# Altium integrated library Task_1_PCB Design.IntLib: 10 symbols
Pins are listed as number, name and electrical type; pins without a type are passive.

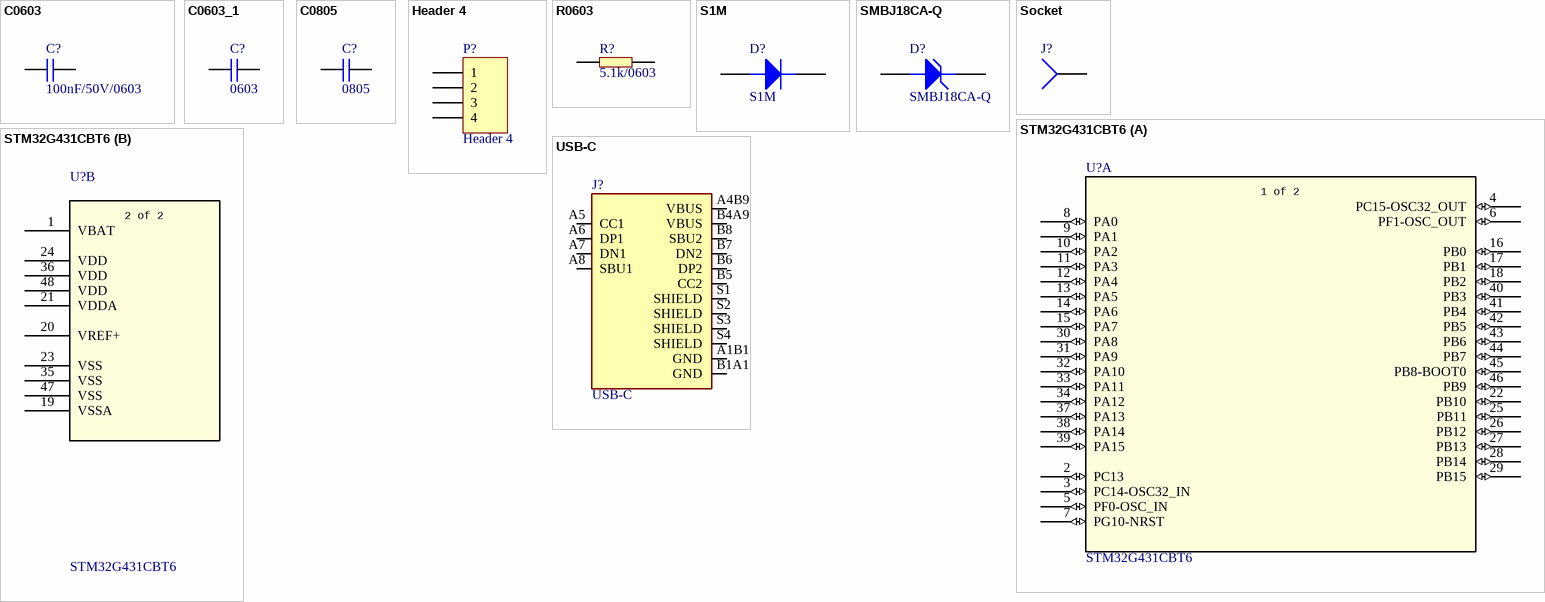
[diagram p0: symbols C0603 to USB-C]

## C0603
designator C?, comment 100nF/50V/0603
footprint C0603
pins: 1, 2

## C0603_1
designator C?, comment 0603
footprint C0603
pins: 1, 2

## C0805
designator C?, comment 0805
footprint C0805
pins: 1, 2

## Header 4
designator P?
Header, 4-Pin
footprint HDR1X4 (Connector; Header; 4 Position)
signal-integrity model Connector
pins: 1, 2, 3, 4

## R0603
designator R?, comment 5.1k/0603
footprint R0603
pins: 1, 2

## S1M
designator D?
VR=1000V IF=1A 6.6pF Trr=1.8us P=1.4W; Manufacturer: ON Semiconductor / Fairchild; Max Reverse Current: 1uA; Recovery Time: 1800ns; Forward Voltage: 1V; Forward Current: 1A; Reverse Recovery Time: 1.8us; Max Repetitive Reverse Voltage (Vrrm): 1kV; Peak Non-Repetitive Surge Current: 30A; Max Surge Current: 40A; Element Configuration: Single; Polarity: Standard; Capacitance: 12pF; Power Dissipation: 1.4W
footprint S1M
pins: A, K

## SMBJ18CA-Q
designator D?
footprint SMBJ18CA-Q
pins: A, K

## Socket
designator J?  (value not drawn)
footprint PIN1 (Connector; Socket)
signal-integrity model Connector
pins: 1

## STM32G431CBT6
designator U?
Mainstream Arm Cortex-M4 MCU 170 MHz with 128 Kbytes of Flash memory, Math Accelerator, Medium Analog level integration; Manufacturer_Name: STMicroelectronics
footprint LQFP48-7x7mm
part A pins: 2 PC13 (io), 3 PC14-OSC32_IN (io), 4 PC15-OSC32_OUT (io), 5 PF0-OSC_IN (io), 6 PF1-OSC_OUT (io), 7 PG10-NRST (io), 8 PA0 (io), 9 PA1 (io), 10 PA2 (io), 11 PA3 (io), 12 PA4 (io), 13 PA5 (io), 14 PA6 (io), 15 PA7 (io), 16 PB0 (io), 17 PB1 (io), 18 PB2 (io), 22 PB10 (io), 25 PB11 (io), 26 PB12 (io), 27 PB13 (io), 28 PB14 (io), 29 PB15 (io), 30 PA8 (io), 31 PA9 (io), 32 PA10 (io), 33 PA11 (io), 34 PA12 (io), 37 PA13 (io), 38 PA14 (io), 39 PA15 (io), 40 PB3 (io), 41 PB4 (io), 42 PB5 (io), 43 PB6 (io), 44 PB7 (io), 45 PB8-BOOT0 (io), 46 PB9 (io)
part B pins: 1 VBAT (power), 19 VSSA (power), 20 VREF+ (power), 21 VDDA (power), 23 VSS (power), 24 VDD (power), 35 VSS (power), 36 VDD (power), 47 VSS (power), 48 VDD (power)

## USB-C
designator J?
USB-C (USB TYPE-C) USB 3.2 Gen 2 (USB 3.1 Gen 2, Superspeed + (USB 3.1)) Receptacle Connector 24 Position Surface Mount, Through Hole; MF: Adam Technologies
footprint HRO_TYPE-C-31-M-12
pins: A1B12 GND (power), A4B9 VBUS (power), A5 CC1 (io), A6 DP1 (io), A7 DN1 (io), A8 SBU1 (io), B1A12 GND (power), B4A9 VBUS (power), B5 CC2 (io), B6 DP2 (io), B7 DN2 (io), B8 SBU2 (io), S1 SHIELD, S2 SHIELD, S3 SHIELD, S4 SHIELD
